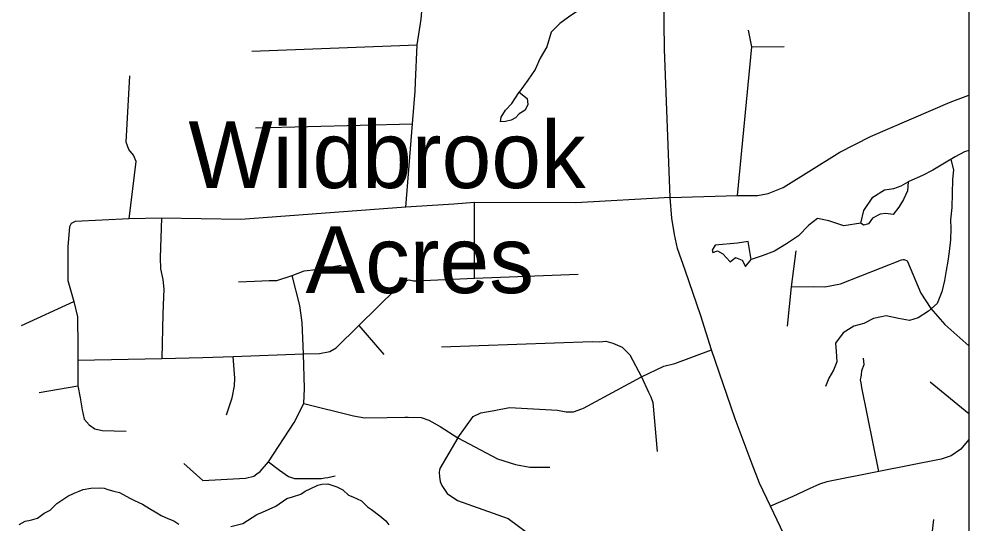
# Model space of a CAD drawing. Extents: x 0 to 69.5, y -4.5 to 22.
# Drawn here: x 7.677 to 8.8, y 16.732 to 17.329 of the extents above; entities that cross this region are included whole.
import ezdxf

# ---------------------------------------------------------------- set-up
doc = ezdxf.new("R2010")
doc.units = 0
for name, color, linetype in [('GM_X_County_Road', 7, 'Continuous'), ('GM_X_Minor_Lake', 7, 'Continuous'), ('GM_X_Minor_River', 7, 'Continuous'), ('GM_X_Township_Subdivision', 7, 'Continuous'), ('GM_X_Unincorporated_Text', 7, 'Continuous'), ('SH_Data', 7, 'Continuous')]:
    doc.layers.add(name, color=color, linetype=linetype)

msp = doc.modelspace()

# ---------------------------------------------------------------- linework, layer by layer
at = {"layer": 'GM_X_County_Road'}
for points in [[(8.6008, 16.6786), (8.5656, 16.7531), (8.5526, 16.7802), (8.5437, 16.8026), (8.5238, 16.8562), (8.4957, 16.9379), (8.4832, 16.978), (8.4645, 17.0319), (8.4556, 17.0577), (8.4518, 17.0743), (8.4489, 17.0933), (8.4467, 17.1179), (8.4403, 17.2932), (8.4393, 17.3556)], [(8.4467, 17.1179), (8.5265, 17.1201), (8.5499, 17.1201), (8.5627, 17.1224), (8.5803, 17.1297), (8.6475, 17.1715), (8.6835, 17.1897), (8.7776, 17.2303), (8.8, 17.2387)]]:
    msp.add_lwpolyline(points, dxfattribs=at)
at = {"layer": 'GM_X_Minor_Lake'}
for points in [[(8.2686, 17.2421), (8.2779, 17.2349), (8.2785, 17.2276), (8.2754, 17.2209), (8.2684, 17.2165), (8.2641, 17.212), (8.2588, 17.2091), (8.2523, 17.2077), (8.2462, 17.2071), (8.2471, 17.2127), (8.2522, 17.221), (8.2596, 17.2288), (8.2631, 17.2344)], [(8.2631, 17.2344), (8.2686, 17.2421)], [(8.728, 17.1364), (8.7275, 17.1257), (8.7227, 17.1156), (8.7172, 17.1066), (8.7105, 17.0976), (8.7018, 17.0989), (8.6949, 17.098), (8.6861, 17.0936), (8.6814, 17.0869), (8.6753, 17.0851), (8.6723, 17.0874), (8.6757, 17.1026), (8.6863, 17.1183), (8.7001, 17.1267), (8.7112, 17.1284), (8.72, 17.1316)], [(8.72, 17.1316), (8.728, 17.1364)], [(8.5426, 17.0444), (8.5389, 17.0657), (8.5263, 17.0637), (8.5001, 17.0616), (8.4965, 17.0556), (8.4972, 17.053), (8.5029, 17.0547), (8.5089, 17.0512), (8.5179, 17.0419), (8.524, 17.0471), (8.532, 17.0438), (8.536, 17.0365)], [(8.536, 17.0365), (8.5426, 17.0444)]]:
    msp.add_lwpolyline(points, dxfattribs=at)
at = {"layer": 'GM_X_Minor_River'}
for points in [[(8.4293, 17.4155), (8.4269, 17.4052), (8.4224, 17.3954), (8.4116, 17.3858), (8.4016, 17.3815), (8.3878, 17.3765), (8.3766, 17.3688), (8.3622, 17.3577), (8.351, 17.3474), (8.3367, 17.3374), (8.3266, 17.3308), (8.3166, 17.3235), (8.3064, 17.3131), (8.3011, 17.2957), (8.2932, 17.2826), (8.2875, 17.269), (8.2788, 17.2563), (8.2686, 17.2421)], [(8.8, 17.1733), (8.7947, 17.1718), (8.7836, 17.1657), (8.7712, 17.1583), (8.7573, 17.1503), (8.745, 17.1438), (8.7289, 17.1369), (8.728, 17.1364)], [(8.7787, 17.1628), (8.7817, 17.1505), (8.7806, 17.1391), (8.7798, 17.106), (8.7783, 17.0916), (8.7785, 17.0813), (8.7781, 17.068), (8.7767, 17.054), (8.7749, 17.0426), (8.7731, 17.0317), (8.7709, 17.0199), (8.7679, 17.0063), (8.7622, 16.9927), (8.7521, 16.9835), (8.7398, 16.9758), (8.7298, 16.9726), (8.7166, 16.9748), (8.7022, 16.9782), (8.6873, 16.9748), (8.6758, 16.969), (8.6639, 16.9659), (8.6512, 16.9578), (8.6422, 16.9459), (8.6431, 16.9359), (8.6439, 16.9237), (8.6399, 16.914), (8.6343, 16.9042), (8.6303, 16.8944)], [(8.6723, 17.0874), (8.6521, 17.0845), (8.6344, 17.0902), (8.6208, 17.0931), (8.6107, 17.085), (8.5987, 17.0727), (8.5844, 17.0632), (8.5702, 17.0544), (8.5556, 17.049), (8.5426, 17.0444)], [(7.6774, 16.7314), (7.6847, 16.7354), (7.6908, 16.7367), (7.6992, 16.7391), (7.707, 16.745), (7.7143, 16.7486), (7.7221, 16.7564), (7.7349, 16.7648), (7.7426, 16.7684), (7.7484, 16.7709), (7.753, 16.7727), (7.7622, 16.7743), (7.7728, 16.7748), (7.7778, 16.7743), (7.7823, 16.773), (7.7895, 16.7709), (7.7963, 16.7692), (7.8083, 16.7628), (7.8139, 16.7599), (7.8188, 16.7575), (7.8233, 16.7555), (7.8315, 16.7503), (7.8401, 16.7451), (7.8454, 16.7423), (7.8532, 16.7386), (7.8604, 16.7358), (7.8664, 16.7318)], [(7.9275, 16.729), (7.9417, 16.7327), (7.9583, 16.7433), (7.9653, 16.7462), (7.981, 16.753), (7.9938, 16.7621), (8.0007, 16.7642), (8.0103, 16.7674), (8.0157, 16.771), (8.0215, 16.7735), (8.0304, 16.7779), (8.0354, 16.7792), (8.0422, 16.7794), (8.0531, 16.7761), (8.0599, 16.7725), (8.0669, 16.7662), (8.0718, 16.7641), (8.082, 16.7593), (8.089, 16.7522), (8.0939, 16.7494), (8.1036, 16.7419), (8.111, 16.736), (8.1143, 16.7313)]]:
    msp.add_lwpolyline(points, dxfattribs=at)
at = {"layer": 'GM_X_Township_Subdivision'}
for points in [[(8.1461, 17.2541), (8.148, 17.2982), (8.1528, 17.3285), (8.1537, 17.3424)], [(8.5265, 17.1201), (8.5434, 17.2959), (8.5393, 17.3155)], [(7.9524, 17.2908), (8.148, 17.2982)], [(8.5434, 17.2959), (8.5816, 17.2961)], [(7.8077, 17.0927), (7.8158, 17.1603), (7.8125, 17.1679), (7.8072, 17.1745), (7.8039, 17.1832), (7.8085, 17.2614)], [(8.1343, 17.1065), (8.1425, 17.2049), (8.1457, 17.2433), (8.1461, 17.2541)], [(7.9567, 17.2002), (8.1425, 17.2049)], [(8.4467, 17.1179), (8.3354, 17.1114), (8.2156, 17.1119), (8.1912, 17.1098), (8.1343, 17.1065), (7.9395, 17.0917), (7.8457, 17.0934), (7.8077, 17.0927), (7.7436, 17.0894), (7.7391, 17.0873), (7.7369, 17.0833)], [(8.2156, 17.0225), (8.2156, 17.1119)], [(7.8457, 17.0934), (7.8442, 17.047), (7.8446, 17.0337), (7.8473, 17.0209), (7.8485, 17.0097), (7.8481, 17.0003), (7.8473, 16.9802), (7.8462, 16.9276)], [(7.7369, 17.0833), (7.7351, 17.0599), (7.7351, 17.0198), (7.7423, 16.9949), (7.7465, 16.9769), (7.7468, 16.9419), (7.7467, 16.9257), (7.7468, 16.8955), (7.7495, 16.8812), (7.7521, 16.8669), (7.7542, 16.856), (7.7602, 16.8491), (7.767, 16.8444), (7.7757, 16.8424), (7.8041, 16.8418)], [(8.5857, 16.9657), (8.5901, 17.0123), (8.5958, 17.0549)], [(8.5901, 17.0123), (8.6166, 17.0127), (8.6295, 17.0122), (8.6481, 17.0158), (8.7201, 17.0443), (8.7222, 17.0445), (8.7233, 17.0444), (8.7243, 17.0442), (8.7261, 17.0435), (8.7268, 17.043), (8.7273, 17.0423), (8.7429, 17.0049), (8.7548, 16.9865), (8.7713, 16.9678), (8.8, 16.9427)], [(7.9368, 17.0182), (7.9556, 17.019), (7.973, 17.0197), (7.9821, 17.0198), (8.0003, 17.0258), (8.0143, 17.031), (8.028, 17.0326), (8.0581, 17.0377)], [(7.7467, 16.9257), (7.8462, 16.9276), (7.8944, 16.9289), (7.9304, 16.9301), (8.0137, 16.933), (8.0324, 16.9334), (8.0446, 16.936), (8.0521, 16.9403), (8.0791, 16.9665), (8.1229, 17.01), (8.1299, 17.0167), (8.1342, 17.0194), (8.1384, 17.0204), (8.1437, 17.0194), (8.1464, 17.0195)], [(7.9583, 16.7912), (7.9622, 16.7941), (7.9721, 16.8056), (8.0024, 16.8521), (8.0139, 16.8743), (8.0146, 16.8921), (8.0137, 16.933), (8.0121, 16.9702), (8.0093, 16.9903), (8.0003, 17.0258)], [(8.1464, 17.0195), (8.2156, 17.0225), (8.3381, 17.0273)], [(7.6802, 16.9665), (7.7423, 16.9949)], [(8.0791, 16.9665), (8.1086, 16.9323)], [(8.1766, 16.9415), (8.3545, 16.9478), (8.3638, 16.9475), (8.3707, 16.948), (8.3792, 16.9459), (8.3903, 16.9409), (8.3991, 16.9319), (8.4128, 16.9061), (8.4211, 16.8879), (8.4241, 16.8822), (8.4263, 16.8757), (8.4314, 16.8176)], [(7.9227, 16.861), (7.9294, 16.8811), (7.9322, 16.8955), (7.9323, 16.9042), (7.9304, 16.9301)], [(8.3444, 16.8691), (8.4128, 16.9061), (8.4392, 16.9184), (8.4522, 16.9218), (8.4957, 16.9379)], [(8.6935, 16.7941), (8.6734, 16.8932), (8.6726, 16.8987), (8.6717, 16.9023), (8.6728, 16.9079), (8.6735, 16.9135), (8.6762, 16.9204), (8.6753, 16.9281)], [(8.8, 16.8622), (8.7543, 16.8996)], [(7.701, 16.8873), (7.7468, 16.8955)], [(8.0139, 16.8743), (8.0728, 16.86), (8.0862, 16.8575), (8.1123, 16.8579), (8.1334, 16.8585), (8.1371, 16.8584)], [(8.1371, 16.8584), (8.1526, 16.8578), (8.1616, 16.8546), (8.175, 16.8473), (8.1959, 16.8338), (8.214, 16.859), (8.2232, 16.8635), (8.2388, 16.8663), (8.2569, 16.8696), (8.3139, 16.8667), (8.324, 16.8645), (8.3328, 16.8648), (8.3423, 16.868), (8.3444, 16.8691)], [(8.1959, 16.8338), (8.1747, 16.7975), (8.1743, 16.7957), (8.174, 16.7932), (8.1742, 16.788), (8.1751, 16.7825), (8.1757, 16.7802), (8.1771, 16.7777), (8.1835, 16.7683), (8.1957, 16.76), (8.2556, 16.7386), (8.28, 16.7203)], [(8.1959, 16.8338), (8.2427, 16.809), (8.2639, 16.8023), (8.2809, 16.7994), (8.3048, 16.7992)], [(8.8, 16.8319), (8.7902, 16.8207), (8.779, 16.8127), (8.7672, 16.8085), (8.6935, 16.7941), (8.6321, 16.782), (8.6233, 16.779), (8.6111, 16.7735), (8.5919, 16.7644), (8.5656, 16.7531)], [(7.872, 16.8034), (7.8946, 16.7836), (7.9449, 16.7863), (7.9547, 16.7886), (7.9583, 16.7912)], [(7.9721, 16.8056), (7.9853, 16.7957), (7.9958, 16.7882), (8.0029, 16.7858), (8.0348, 16.7858), (8.0386, 16.7866), (8.0424, 16.7872), (8.0509, 16.7891)], [(8.7296, 16.5395), (8.7311, 16.5659), (8.7522, 16.683), (8.7585, 16.7373)]]:
    msp.add_lwpolyline(points, dxfattribs=at)
at = {"layer": 'SH_Data'}
msp.add_line((8.8, 21), (8.8, 14.2), dxfattribs=at)

# ---------------------------------------------------------------- texts
at = {"layer": 'GM_X_Unincorporated_Text'}
for s, p in [('Wildbrook', (7.8775, 17.129)), ('Acres', (8.0159, 17.0049))]:
    msp.add_text(s, height=0.07898, rotation=0, dxfattribs=at).set_placement(p)

doc.saveas('drawing.dxf')
